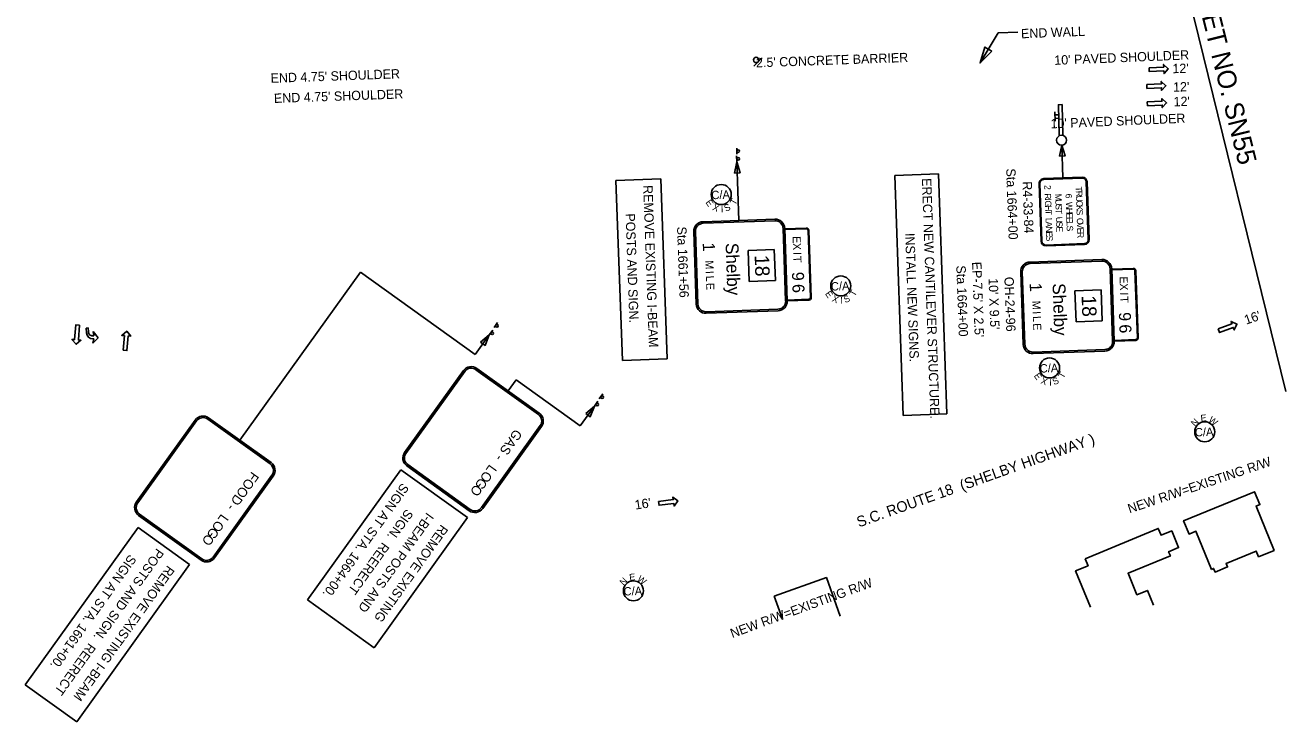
# Model space of a CAD drawing. Extents: x 1811940 to 1813538, y 1189643 to 1190703.
# Drawn here: x 1812593 to 1813538, y 1189718 to 1190240 of the extents above; entities that cross this region are included whole.
import ezdxf

# ---------------------------------------------------------------- set-up
doc = ezdxf.new("R2010")
doc.units = 0
for name, color, linetype in [('RD_EX_Bldg', 7, 'Continuous'), ('RD_PD_Final_LnLine', 7, 'Continuous'), ('RD_PD_Final_TX', 7, 'Continuous'), ('RD_PD_RW_TX', 7, 'Continuous'), ('RD_SHT_MatchLine', 7, 'Continuous'), ('RD_SHT_TX', 7, 'Continuous'), ('RD_Sketch10', 7, 'Continuous'), ('RD_Sketch8', 7, 'Continuous'), ('RD_TX_RoadID', 7, 'Continuous'), ('SN_P_Signs', 7, 'Continuous'), ('TERMINATOR', 7, 'Continuous')]:
    doc.layers.add(name, color=color, linetype=linetype)

# ---------------------------------------------------------------- blocks, each defined once
blk = doc.blocks.new('SARRW2')
at = {"layer": 'RD_PD_Final_LnLine'}
blk.add_lwpolyline([(-12, 1.2), (-12, -1.2), (-2.83, -1.2), (-2.83, -2.83), (0, 0), (-2.83, 2.83), (-2.83, 1.2)], close=True, dxfattribs=at)

msp = doc.modelspace()

# ---------------------------------------------------------------- linework, layer by layer
at = {"layer": 'RD_EX_Bldg'}
for points in [[(1813482.59, 1189832.06), (1813470.9, 1189860.66), (1813465.72, 1189858.55), (1813461.67, 1189868.47), (1813514.89, 1189890.22), (1813518.79, 1189880.66), (1813515.94, 1189879.49), (1813529.51, 1189846.27), (1813517.84, 1189841.5), (1813516.1, 1189845.75), (1813493.52, 1189836.53), (1813494.62, 1189833.84), (1813485.27, 1189830.02), (1813484.18, 1189832.71), (1813482.59, 1189832.06)], [(1813439.03, 1189805.25), (1813434.5, 1189816.21), (1813426.7, 1189812.99), (1813420.05, 1189829.09), (1813451.72, 1189842.18), (1813450.45, 1189845.26), (1813457.89, 1189848.34), (1813452.72, 1189860.86), (1813444.8, 1189857.58), (1813442.68, 1189862.71), (1813387.81, 1189840.03)], [(1813387.81, 1189840.03), (1813390.02, 1189834.7), (1813380.64, 1189830.82), (1813391.89, 1189803.59)], [(1813204.25, 1189796.97), (1813193.89, 1189825.93), (1813154.78, 1189811.93)], [(1813154.78, 1189811.93), (1813160.68, 1189795.44)]]:
    msp.add_lwpolyline(points, dxfattribs=at)
at = {"layer": 'RD_PD_Final_LnLine'}
for p, q in [((1812640.6, 1190012.95), (1812639.16, 1190012.9)), ((1812640.6, 1190012.95), (1812639.16, 1190012.9)), ((1812639.16, 1190012.9), (1812639.29, 1190009.26)), ((1812639.16, 1190012.9), (1812639.29, 1190009.26)), ((1812640.69, 1190010.17), (1812640.6, 1190012.95)), ((1812640.6, 1190012.95), (1812640.6, 1190012.95)), ((1812640.69, 1190010.17), (1812640.6, 1190012.95)), ((1812640.6, 1190012.95), (1812640.6, 1190012.95)), ((1812644.84, 1190007.05), (1812643.98, 1190007.02)), ((1812644.84, 1190007.05), (1812643.98, 1190007.02)), ((1812644.17, 1190001.55), (1812648.11, 1190005.48)), ((1812644.17, 1190001.55), (1812648.11, 1190005.48)), ((1812648.11, 1190005.48), (1812644.24, 1190010.3)), ((1812644.24, 1190010.3), (1812644.84, 1190007.05)), ((1812648.11, 1190005.48), (1812644.24, 1190010.3)), ((1812644.24, 1190010.3), (1812644.84, 1190007.05)), ((1812644.06, 1190004.72), (1812644.92, 1190004.75)), ((1812644.06, 1190004.72), (1812644.92, 1190004.75)), ((1812644.92, 1190004.75), (1812644.17, 1190001.55)), ((1812644.92, 1190004.75), (1812644.17, 1190001.55))]:
    msp.add_line(p, q, dxfattribs=at)
for centre, radius, start, end in [((1812643.99, 1190009.42), 4.7, 182.00645, 270.849), ((1812643.99, 1190009.42), 4.7, 182.00645, 270.849), ((1812643.86, 1190010.19), 3.17, 180.28187, 272.04469), ((1812643.86, 1190010.19), 3.17, 180.28187, 272.04469)]:
    msp.add_arc(centre, radius, start, end, dxfattribs=at)
at = {"layer": 'RD_PD_Final_TX'}
for p, q in [((1813322.74, 1190234.22), (1813309.15, 1190211.61)), ((1813337.38, 1190234.8), (1813322.74, 1190234.22))]:
    msp.add_line(p, q, dxfattribs=at)
at = {"layer": 'RD_SHT_MatchLine'}
msp.add_line((1813379.72, 1190611.46), (1813538.24, 1189965.46), dxfattribs=at)
at = {"layer": 'RD_Sketch10'}
for centre in [(1813477.47, 1189935.16), (1813049.26, 1189815.94)]:
    msp.add_circle(centre, 7.5, dxfattribs=at)
at = {"layer": 'RD_Sketch8'}
for centre in [(1813115.06, 1190112.98), (1813204.67, 1190044.51), (1813361.17, 1189983.02)]:
    msp.add_circle(centre, 7.5, dxfattribs=at)
at = {"layer": 'SN_P_Signs'}
for p, q in [((1813139.48, 1190209.2), (1813145.84, 1190215.56)), ((1813365.39, 1190167.99), (1813365.21, 1190174.95)), ((1813368.02, 1190172.84), (1813365.24, 1190172.77)), ((1813368.09, 1190170.17), (1813365.32, 1190170.09)), ((1813126.7, 1190147.82), (1813126.86, 1190143.33)), ((1813371.19, 1190125.43), (1813370.33, 1190150.02)), ((1813126.61, 1190141.91), (1813126.77, 1190137.41)), ((1813128.31, 1190093.57), (1813126.77, 1190137.41)), ((1813245.16, 1190127.25), (1813277.94, 1190128.4)), ((1813277.94, 1190128.4), (1813284.28, 1189948.51)), ((1813036.19, 1190123.47), (1813069.79, 1190124.66)), ((1813040.95, 1189988.54), (1813036.19, 1190123.47)), ((1813069.79, 1190124.66), (1813074.55, 1189989.72)), ((1813251.5, 1189947.36), (1813245.16, 1190127.25)), ((1813155.25, 1190093.32), (1813101.45, 1190091.43)), ((1813135.15, 1190070.97), (1813154.82, 1190071.67)), ((1813135.96, 1190047.92), (1813135.15, 1190070.97)), ((1813400.33, 1190063.09), (1813346.52, 1190061.2)), ((1812754.26, 1189928.82), (1812844.7, 1190054.78)), ((1812930.65, 1189993.07), (1812844.7, 1190054.78)), ((1813155.64, 1190048.61), (1813135.96, 1190047.92)), ((1813380.22, 1190040.75), (1813399.9, 1190041.44)), ((1813381.03, 1190017.69), (1813380.22, 1190040.75)), ((1813103.79, 1190025.15), (1813157.59, 1190027.04)), ((1812947.5, 1190016.98), (1812944.87, 1190013.33)), ((1813400.71, 1190018.39), (1813381.03, 1190017.69)), ((1812930.65, 1189993.07), (1812941.2, 1190007.76)), ((1812943.83, 1190011.42), (1812941.2, 1190007.76)), ((1813348.86, 1189994.92), (1813402.66, 1189996.82)), ((1813074.55, 1189989.72), (1813040.95, 1189988.54)), ((1812955.33, 1189965.9), (1812961.3, 1189974.21)), ((1813009.44, 1189939.64), (1812961.3, 1189974.21)), ((1813022.62, 1189957.99), (1813019.99, 1189954.34)), ((1813026.29, 1189963.56), (1813023.66, 1189959.9)), ((1813009.44, 1189939.64), (1813019.99, 1189954.34)), ((1813284.28, 1189948.51), (1813251.5, 1189947.36)), ((1812804.93, 1189809.27), (1812874.93, 1189906.76)), ((1812874.93, 1189906.76), (1812924.98, 1189870.82)), ((1812593.37, 1189745.58), (1812677.96, 1189863.37)), ((1812677.96, 1189863.37), (1812716.63, 1189835.6)), ((1812924.98, 1189870.82), (1812854.98, 1189773.33)), ((1812716.63, 1189835.6), (1812632.05, 1189717.8)), ((1812854.98, 1189773.33), (1812804.93, 1189809.27)), ((1812632.05, 1189717.8), (1812593.37, 1189745.58))]:
    msp.add_line(p, q, dxfattribs=at)
for points in [[(1813371.23, 1190157.27), (1813370.61, 1190180.4), (1813367.82, 1190180.32), (1813368.44, 1190157.01)], [(1813353.33, 1190121.19), (1813354.85, 1190078.02)], [(1813353.93, 1190121.21), (1813355.45, 1190078.04)], [(1813385.59, 1190125.93), (1813356.8, 1190124.92)], [(1813385.61, 1190125.33), (1813356.82, 1190124.32)], [(1813390.23, 1190079.27), (1813388.71, 1190122.44)], [(1813390.83, 1190079.29), (1813389.31, 1190122.46)], [(1813155.21, 1190094.52), (1813101.41, 1190092.62)], [(1813094.47, 1190085.18), (1813096.38, 1190030.89)], [(1813095.67, 1190085.22), (1813097.58, 1190030.93)], [(1813163.37, 1190033.25), (1813161.46, 1190087.54)], [(1813164.57, 1190033.29), (1813162.66, 1190087.58)], [(1813178.88, 1190087.23), (1813162.69, 1190086.66), (1813162.67, 1190087.26), (1813178.86, 1190087.83)], [(1813181.9, 1190035.71), (1813180.12, 1190086.07)], [(1813180.72, 1190086.1), (1813182.5, 1190035.73)], [(1813154.82, 1190071.67), (1813155.64, 1190048.61)], [(1813358.56, 1190075.15), (1813387.34, 1190076.16)], [(1813358.58, 1190074.55), (1813387.36, 1190075.56)], [(1813400.28, 1190064.29), (1813346.48, 1190062.4)], [(1813339.54, 1190054.95), (1813341.45, 1190000.66)], [(1813340.74, 1190054.99), (1813342.65, 1190000.71)], [(1813408.45, 1190003.02), (1813406.53, 1190057.31)], [(1813409.65, 1190003.07), (1813407.73, 1190057.35)], [(1813423.96, 1190057), (1813407.77, 1190056.43), (1813407.74, 1190057.03), (1813423.93, 1190057.6)], [(1813426.97, 1190005.48), (1813425.2, 1190055.85)], [(1813425.8, 1190055.87), (1813427.57, 1190005.5)], [(1813164.55, 1190033.89), (1813180.74, 1190034.46)], [(1813180.76, 1190033.86), (1813164.57, 1190033.29), (1813164.55, 1190033.89)], [(1813399.9, 1190041.44), (1813400.71, 1190018.39)], [(1813103.83, 1190023.95), (1813157.63, 1190025.84)], [(1813348.9, 1189993.72), (1813402.7, 1189995.62)], [(1813409.63, 1190003.67), (1813425.82, 1190004.24)], [(1813425.84, 1190003.64), (1813409.65, 1190003.07), (1813409.63, 1190003.67)], [(1812877.79, 1189919.64), (1812921.88, 1189981.05)], [(1812878.76, 1189918.94), (1812922.86, 1189980.35)], [(1812931.23, 1189981.72), (1812978.02, 1189948.12)], [(1812931.93, 1189982.69), (1812978.72, 1189949.1)], [(1812676.73, 1189882.56), (1812720.82, 1189943.97)], [(1812677.7, 1189881.86), (1812721.79, 1189943.27)], [(1812730.17, 1189944.65), (1812776.96, 1189911.05)], [(1812730.87, 1189945.62), (1812777.66, 1189912.03)], [(1812979.39, 1189939.75), (1812935.3, 1189878.34)], [(1812980.37, 1189939.05), (1812936.27, 1189877.64)], [(1812926.93, 1189876.97), (1812880.14, 1189910.56)], [(1812778.33, 1189902.68), (1812734.24, 1189841.27)], [(1812779.3, 1189901.98), (1812735.21, 1189840.57)], [(1812926.23, 1189875.99), (1812879.44, 1189909.59)], [(1812725.86, 1189839.89), (1812679.07, 1189873.49)], [(1812725.16, 1189838.92), (1812678.37, 1189872.52)]]:
    msp.add_lwpolyline(points, dxfattribs=at)
for points in [[(1813368.66, 1190141.73), (1813370.33, 1190150.02), (1813372.76, 1190141.92)], [(1813125.14, 1190129.12), (1813126.81, 1190137.41), (1813129.24, 1190129.31)], [(1812934.75, 1190002.29), (1812941.2, 1190007.76), (1812938.08, 1189999.9)], [(1813013.54, 1189948.87), (1813019.99, 1189954.34), (1813016.87, 1189946.48)]]:
    msp.add_lwpolyline(points, close=True, dxfattribs=at)
for centre, radius in [((1813141.24, 1190213.83), 2), ((1813370.16, 1190153.72), 3.71), ((1813127.79, 1190145.6), 1), ((1813127.7, 1190139.68), 1), ((1812947, 1190014.56), 1), ((1812943.33, 1190008.99), 1), ((1813025.79, 1189961.13), 1), ((1813022.12, 1189955.57), 1)]:
    msp.add_circle(centre, radius, dxfattribs=at)
for centre, radius, start, end in [((1813356.93, 1190121.32), 3.6, 92.01838, 182.01838), ((1813356.93, 1190121.32), 3, 92.01838, 182.01838), ((1813385.71, 1190122.33), 3.6, 2.01838, 92.01838), ((1813385.71, 1190122.33), 3, 2.01838, 92.01838), ((1813101.66, 1190085.43), 7.2, 92.01838, 182.01838), ((1813101.66, 1190085.43), 6, 92.01838, 182.01838), ((1813155.47, 1190087.33), 7.2, 2.01838, 92.01838), ((1813155.47, 1190087.33), 6, 2.01838, 92.01838), ((1813178.93, 1190086.03), 1.8, 2.01838, 92.01838), ((1813178.93, 1190086.03), 1.2, 2.01838, 92.01838), ((1813358.45, 1190078.15), 3.6, 182.01838, 272.01838), ((1813358.45, 1190078.15), 3, 182.01838, 272.01838), ((1813387.23, 1190079.16), 3, 272.01838, 2.01838), ((1813387.23, 1190079.16), 3.6, 272.01838, 2.01838), ((1813346.73, 1190055.2), 7.2, 92.01838, 182.01838), ((1813400.54, 1190057.1), 7.2, 2.01838, 92.01838), ((1813400.54, 1190057.1), 6, 2.01838, 92.01838), ((1813346.73, 1190055.2), 6, 92.01838, 182.01838), ((1813424, 1190055.8), 1.8, 2.01838, 92.01838), ((1813424, 1190055.8), 1.2, 2.01838, 92.01838), ((1813157.38, 1190033.04), 6, 272.01838, 2.01838), ((1813157.38, 1190033.04), 7.2, 272.01838, 2.01838), ((1813180.7, 1190035.66), 1.2, 272.01838, 2.01838), ((1813180.7, 1190035.66), 1.8, 272.01838, 2.01838), ((1813103.58, 1190031.14), 7.2, 182.01838, 272.01838), ((1813103.58, 1190031.14), 6, 182.01838, 272.01838), ((1813425.77, 1190005.44), 1.2, 272.01838, 2.01838), ((1813425.77, 1190005.44), 1.8, 272.01838, 2.01838), ((1813348.65, 1190000.92), 7.2, 182.01838, 272.01838), ((1813348.65, 1190000.92), 6, 182.01838, 272.01838), ((1813402.45, 1190002.81), 6, 272.01838, 2.01838), ((1813402.45, 1190002.81), 7.2, 272.01838, 2.01838), ((1812927.73, 1189976.85), 7.2, 54.32003, 144.32003), ((1812927.73, 1189976.85), 6, 54.32003, 144.32003), ((1812974.52, 1189943.25), 7.2, 324.32003, 54.32003), ((1812726.67, 1189939.77), 7.2, 54.32003, 144.32003), ((1812726.67, 1189939.77), 6, 54.32003, 144.32003), ((1812974.52, 1189943.25), 6, 324.32003, 54.32003), ((1812773.46, 1189906.18), 6, 324.32003, 54.32003), ((1812773.46, 1189906.18), 7.2, 324.32003, 54.32003), ((1812883.64, 1189915.44), 7.2, 144.32003, 234.32003), ((1812883.64, 1189915.44), 6, 144.32003, 234.32003), ((1812682.57, 1189878.36), 7.2, 144.32003, 234.32003), ((1812682.57, 1189878.36), 6, 144.32003, 234.32003), ((1812930.43, 1189881.84), 7.2, 234.32003, 324.32003), ((1812930.43, 1189881.84), 6, 234.32003, 324.32003), ((1812729.36, 1189844.77), 7.2, 234.32003, 324.32003), ((1812729.36, 1189844.77), 6, 234.32003, 324.32003)]:
    msp.add_arc(centre, radius, start, end, dxfattribs=at)
at = {"layer": 'TERMINATOR'}
msp.add_lwpolyline([(1813317.9, 1190220.35), (1813309.15, 1190211.61), (1813312.76, 1190223.44)], close=True, dxfattribs=at)

# ---------------------------------------------------------------- block references
at = {"layer": 'RD_PD_Final_LnLine'}
for p, xscale, yscale, rotation in [((1813450.2, 1190207.21), 1.1999999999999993, 1.2, 2.520309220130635), ((1813448.44, 1190194.56), 1.1999999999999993, 1.2, 2.520309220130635), ((1813448.91, 1190181.65), 1.1999999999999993, 1.2, 2.520309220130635), ((1812631.48, 1190000.73), 1.2, 1.2000000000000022, -94.87917073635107), ((1813501.58, 1190015.92), 1.1999999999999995, 1.1999999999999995, 20.52938511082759), ((1812669.44, 1190010.48), 1.2000000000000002, 1.2000000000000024, 85.12082926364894), ((1813082.64, 1189883.31), 1.1999999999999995, 1.1999999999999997, 7.100644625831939)]:
    msp.add_blockref('SARRW2', p, dxfattribs=dict(at, xscale=xscale, yscale=yscale, rotation=rotation))

# ---------------------------------------------------------------- texts
at = {"layer": 'RD_PD_Final_TX'}
for s, rotation, p in [('END WALL', 2.26838, (1813339.91, 1190230.05)), ("2.5' CONCRETE BARRIER", 2.02012, (1813141.25, 1190208.29)), ("10' PAVED SHOULDER", 2.33035, (1813364.86, 1190210.13)), ("END 4.75' SHOULDER", 2.01838, (1812777.43, 1190196.68)), ("12'", 1.2914, (1813453.32, 1190203.9)), ("12'", 1.2914, (1813453.81, 1190190.06)), ("END 4.75' SHOULDER", 2.01838, (1812779.92, 1190181.6)), ("12'", 1.2914, (1813454.2, 1190179.11)), ("10' PAVED SHOULDER", 2.40704, (1813362.03, 1190162.55)), ("16'", 19.07248, (1813508.54, 1190015.42)), ("16'", 8.51249, (1813050.76, 1189876.83))]:
    msp.add_text(s, height=7, rotation=rotation, dxfattribs=at).set_placement(p)
at = {"layer": 'RD_PD_RW_TX'}
for rotation, p in [(18.6236, (1813421.16, 1189873.94)), (20.15345, (1813123.4, 1189780.48))]:
    msp.add_text('NEW R/W=EXISTING R/W', height=7, rotation=rotation, dxfattribs=at).set_placement(p)
at = {"layer": 'RD_SHT_TX'}
msp.add_text('MATCHLINE STA. 1665+00 SEE SHEET NO. SN55', height=14.1726, rotation=283.90674, dxfattribs=at).set_placement((1813397.34, 1190561.08))
at = {"layer": 'RD_Sketch10'}
for s, height, rotation, p in [('E', 5, 6.35143, (1813474.63, 1189942.77)), ('N', 5, 46.88815, (1813470.21, 1189938.75)), ('W', 5, 321.321, (1813479.8, 1189943.21)), ('C/A', 6.25, 2.01838, (1813470.17, 1189931.63)), ('N', 5, 46.88815, (1813042, 1189819.52)), ('E', 5, 6.35143, (1813046.42, 1189823.55)), ('W', 5, 321.321, (1813051.6, 1189823.98)), ('C/A', 6.25, 2.01838, (1813041.97, 1189812.4))]:
    msp.add_text(s, height=height, rotation=rotation, dxfattribs=at).set_placement(p)
at = {"layer": 'RD_Sketch8'}
for s, height, rotation, p in [('E', 5, 305.22963, (1813103.04, 1190107.03)), ('C/A', 6.25, 2.01838, (1813107.77, 1190109.44)), ('T', 5, 60.20353, (1813125.55, 1190104.64)), ('X', 5, 337.659, (1813108.02, 1190101.55)), ('I', 5, 1.819, (1813114.87, 1190099.72)), ('S', 5, 23.81082, (1813118.51, 1190100.02)), ('C/A', 6.25, 2.01838, (1813197.37, 1190040.97)), ('E', 5, 305.22963, (1813192.65, 1190038.56)), ('X', 5, 337.659, (1813197.62, 1190033.08)), ('I', 5, 1.819, (1813204.47, 1190031.25)), ('S', 5, 23.81082, (1813208.12, 1190031.55)), ('T', 5, 60.20353, (1813215.16, 1190036.17)), ('C/A', 6.25, 2.01838, (1813353.88, 1189979.48)), ('E', 5, 305.22963, (1813349.15, 1189977.07)), ('T', 5, 60.20353, (1813371.66, 1189974.67)), ('X', 5, 337.659, (1813354.13, 1189971.59)), ('I', 5, 1.819, (1813360.98, 1189969.75)), ('S', 5, 23.81082, (1813364.62, 1189970.06))]:
    msp.add_text(s, height=height, rotation=rotation, dxfattribs=at).set_placement(p)
at = {"layer": 'RD_TX_RoadID'}
msp.add_text('S.C. ROUTE 18  (SHELBY HIGHWAY )', height=8, rotation=19.58277, dxfattribs=at).set_placement((1813218.29, 1189863.41))
at = {"layer": 'SN_P_Signs'}
for s, height, rotation, p in [('Sta 1664+00', 7, 272.01846, (1813328.65, 1190132.41)), ('REMOVE EXISTING I-BEAM', 6.9998, 272.01846, (1813056.59, 1190119.9)), ('ERECT NEW CANTILEVER STRUCTURE.', 7, 272.01846, (1813265.5, 1190125.12)), ('R4-33-84', 7, 272.01846, (1813340.9, 1190122.75)), ('2', 4.8, 272.01838, (1813357.28, 1190120.02)), ('T', 4.8, 272.01838, (1813380.73, 1190118.92)), ('R', 4.8, 272.01838, (1813357.5, 1190113.8)), ('I', 4.8, 272.01838, (1813357.62, 1190110.16)), ('M', 4.8, 272.01838, (1813365.31, 1190113.44)), ('U', 4.8, 272.01838, (1813365.46, 1190109.32)), ('6', 4.8, 272.01838, (1813373.11, 1190113.55)), ('R', 4.8, 272.01838, (1813380.84, 1190115.72)), ('U', 4.8, 272.01838, (1813380.97, 1190112.08)), ('G', 4.8, 272.01838, (1813357.68, 1190108.48)), ('H', 4.8, 272.01838, (1813357.81, 1190104.84)), ('T', 4.8, 272.01838, (1813357.93, 1190101.41)), ('S', 4.8, 272.01838, (1813365.59, 1190105.69)), ('T', 4.8, 272.01838, (1813365.71, 1190102.26)), ('W', 4.8, 272.01838, (1813373.33, 1190107.33)), ('H', 4.8, 272.01838, (1813373.49, 1190102.92)), ('C', 4.8, 272.01838, (1813381.1, 1190108.45)), ('K', 4.8, 272.01838, (1813381.22, 1190105.02)), ('S', 4.8, 272.01838, (1813381.34, 1190101.58)), ('POSTS AND SIGN.', 6.9998, 272.01846, (1813043.33, 1190098.71)), ('L', 4.8, 272.01838, (1813358.14, 1190095.41)), ('A', 4.8, 272.01838, (1813358.24, 1190092.74)), ('U', 4.8, 272.01838, (1813365.92, 1190096.26)), ('S', 4.8, 272.01838, (1813366.05, 1190092.63)), ('E', 4.8, 272.01838, (1813373.62, 1190099.29)), ('E', 4.8, 272.01838, (1813373.73, 1190096.08)), ('L', 4.8, 272.01838, (1813373.84, 1190092.87)), ('O', 4.8, 272.01838, (1813381.56, 1190095.36)), ('V', 4.8, 272.01838, (1813381.69, 1190091.78)), ('Sta 1661+56', 7, 272.01846, (1813081.96, 1190088.86)), ('E', 6, 272.01838, (1813168.57, 1190081.73)), ('INSTALL NEW SIGNS.', 7, 272.01846, (1813252.94, 1190084.03)), ('N', 4.8, 272.01838, (1813358.37, 1190088.94)), ('E', 4.8, 272.01838, (1813358.5, 1190085.3)), ('S', 4.8, 272.01838, (1813358.61, 1190082.09)), ('E', 4.8, 272.01838, (1813366.17, 1190088.99)), ('S', 4.8, 272.01838, (1813373.96, 1190089.66)), ('E', 4.8, 272.01838, (1813381.82, 1190088.04)), ('R', 4.8, 272.01838, (1813381.93, 1190084.84)), ('1', 9, 272.01838, (1813101.19, 1190076.86)), ('Shelby', 9.6, 272.01838, (1813118.32, 1190076.56)), ('X', 6, 272.01838, (1813168.75, 1190076.58)), ('M', 6, 272.01838, (1813103.16, 1190063.53)), ('18', 10.8, 272.01838, (1813140.11, 1190067.44)), ('I', 6, 272.01838, (1813168.99, 1190069.77)), ('T', 6, 272.01838, (1813169.1, 1190066.79)), ("EP-7.5' X 2.5'", 7, 272.01846, (1813303.08, 1190062.48)), ('I', 6, 272.01838, (1813103.44, 1190055.67)), ('9', 9, 272.01838, (1813168.02, 1190054.87)), ('Sta 1664+00', 7, 272.01846, (1813291.27, 1190059.74)), ('L', 6, 272.01838, (1813103.56, 1190052.08)), ('E', 6, 272.01838, (1813103.76, 1190046.66)), ('6', 9, 272.01838, (1813168.34, 1190045.78)), ("10' X 9.5'", 7, 272.01846, (1813315.42, 1190050.17)), ('OH-24-96', 7, 272.01846, (1813327.29, 1190051.2)), ('1', 9, 272.01838, (1813346.26, 1190046.64)), ('Shelby', 9.6, 272.01838, (1813363.39, 1190046.34)), ('E', 6, 272.01838, (1813413.64, 1190051.5)), ('X', 6, 272.01838, (1813413.82, 1190046.35)), ('18', 10.8, 272.01838, (1813385.18, 1190037.21)), ('I', 6, 272.01838, (1813414.06, 1190039.55)), ('T', 6, 272.01838, (1813414.17, 1190036.56)), ('M', 6, 272.01838, (1813348.23, 1190033.3)), ('I', 6, 272.01838, (1813348.51, 1190025.44)), ('9', 9, 272.01838, (1813413.09, 1190024.65)), ('L', 6, 272.01838, (1813348.64, 1190021.85)), ('E', 6, 272.01838, (1813348.83, 1190016.43)), ('6', 9, 272.01838, (1813413.41, 1190015.55)), ('GAS', 7.2, 234.32003, (1812960.55, 1189937.68)), ('L', 7.2, 234.32003, (1812941.48, 1189911.12)), ('-', 7.2, 234.32003, (1812946.94, 1189918.73)), ('FOOD', 7.2, 234.32003, (1812763.21, 1189905.8)), ('O', 7.2, 234.32003, (1812938.13, 1189906.46)), ('SIGN AT STA. 1664+00.', 6.9998, 234.32011, (1812875.81, 1189897.25)), ('O', 7.2, 234.32003, (1812930.78, 1189896.23)), ('G', 7.2, 234.32003, (1812934.39, 1189901.25)), ('L', 7.2, 234.32003, (1812740.41, 1189874.05)), ('-', 7.2, 234.32003, (1812745.88, 1189881.66)), ('SIGN.  REERECT', 6.9998, 234.32011, (1812879.05, 1189877.76)), ('I-BEAM POSTS AND', 6.9998, 234.32011, (1812894.44, 1189875.2)), ('O', 7.2, 234.32003, (1812737.07, 1189869.39)), ('REMOVE EXISTING', 6.9998, 234.32011, (1812905.16, 1189866.12)), ('O', 7.2, 234.32003, (1812729.72, 1189859.15)), ('G', 7.2, 234.32003, (1812733.33, 1189864.18)), ('POSTS AND SIGN.  REERECT', 6.9998, 234.32011, (1812692.05, 1189848.28)), ('SIGN AT STA. 1661+00.', 6.9998, 234.32011, (1812671.54, 1189843.71)), ('REMOVE EXISTING I-BEAM', 6.9998, 234.32011, (1812700.1, 1189835.48))]:
    msp.add_text(s, height=height, rotation=rotation, dxfattribs=at).set_placement(p)

doc.saveas('drawing.dxf')
